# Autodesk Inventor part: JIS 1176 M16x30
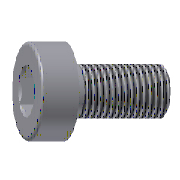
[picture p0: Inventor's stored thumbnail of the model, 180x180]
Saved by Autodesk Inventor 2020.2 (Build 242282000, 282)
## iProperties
Created: 2019-01
Part Number: JIS 1176 M16x30
Material: Stal, miękka
Description: Wkręt z łbem półkolistym walcowym
Document SubType Name: Modeling
Designer: F.Stasiak
Standard Revision: 1
Language: pl-PL
Size Designation: M16x30
Categories: <MemberInstance><Categories><Category DisplayName="Forma wtryskowa" InternalName="349578f2-f4d4-4954-8c09-8e99297a61c0" Mnemonic="MOLD"><Category DisplayName="C
Mass: 0.133121 g
Surface Area: 2.01441 cm^2
Volume: 0.133121 cm^3
Density: 7.85 g/cm^3
Appearance: Częściowo polerowany
Catalog Web Link: www.expertbooks.pl
Manager: www.cadconsulting.pl
Company: Fabian Stasiak CAD Consulting
IsCustomPart: 0
Author: F.Stasiak
Subject: Zbiór ćwiczeń. Autodesk Inventor 2020. Kurs Professional
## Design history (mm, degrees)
body "Solid1"
revolve "Obrót1" stored, may be unused: angle "d44" = 90 deg
sketch "Sketch2"
  geometry: L1 (0, 8.083)-(7, 4.041); L2 (7, 4.041)-(7, -4.041); L3 (7, -4.041)-(0, -8.083); L4 (0, -8.083)-(-7, -4.041); L5 (-7, -4.041)-(-7, 4.041); L6 (-7, 4.041)-(0, 8.083); 3 further points
  constraints: 12 end point, 2 vertical alignment, 1 coincident, 14 other
extrude "Wyciągnięcie proste1" cut sketch "Sketch2" taper "d9" = 0 deg; stored distance "d45" = 10
feature "Gwint1" dims "d10" = 25 (= b), "d11" = 0
chamfer "Faza1" distance "d12" = 1 (= 0.5 x P); stored, may be unused: second distance "d50" = 2, angle "d51" = 45 deg
fillet "Zaokrąglenie1" dims "d13" = 1 (= 0.5 x P)
sketch "Sketch1"
  geometry: L1 (0, -39.2)-(0, 25.2) reference; L2 (8.083, 16)-(12, 16); L3 (12, 16)-(12, 0); L4 (12, 0)-(8, 0); L5 (8, 0)-(8, -30); L6 (8, -30)-(0, -30); L7 (0, 3.794)-(0, -30); L8 (0, 3.794)-(7, 8); L9 (7, 8)-(7, 14.917); L10 (7, 14.917)-(8.083, 16); 1 further point
  constraints: 18 end point, 4 vertical, 3 horizontal, 2 point on line
  dimensions: "d0" = 24 diameter of L3 L1 (= dk); "d1" = 16 distance between parallel lines of L4 L2 (= k); "d2" = 16 diameter of L5 L1 (= d); "d3" = 30 distance between parallel lines of L6 L4 (= L); "d4" = 59 deg angle of L1 L8; "d5" = 45 deg angle of L1 L10; "d6" = 14 diameter of L9 L1 (= sw); "d7" = 16.16581 diameter of L2.start L1 (= 1.1547 x sw); "d8" = 8 distance from line of L8.end L2 (= t)
other parameters: "d" = 16 [user parameter; used in 1 equation term], "L" = 30 [user parameter; used in 1 equation term], "dk" = 24 [user parameter; used in 1 equation term], "b" = 25 [user parameter; used in 1 equation term], "k" = 16 [user parameter; used in 1 equation term], "sw" = 14 [user parameter; used in 2 equation terms], "t" = 8 [user parameter; used in 1 equation term], "P" = 2 [user parameter; used in 2 equation terms], "d14" = 0, "d15" = 0, "d55" = 0
